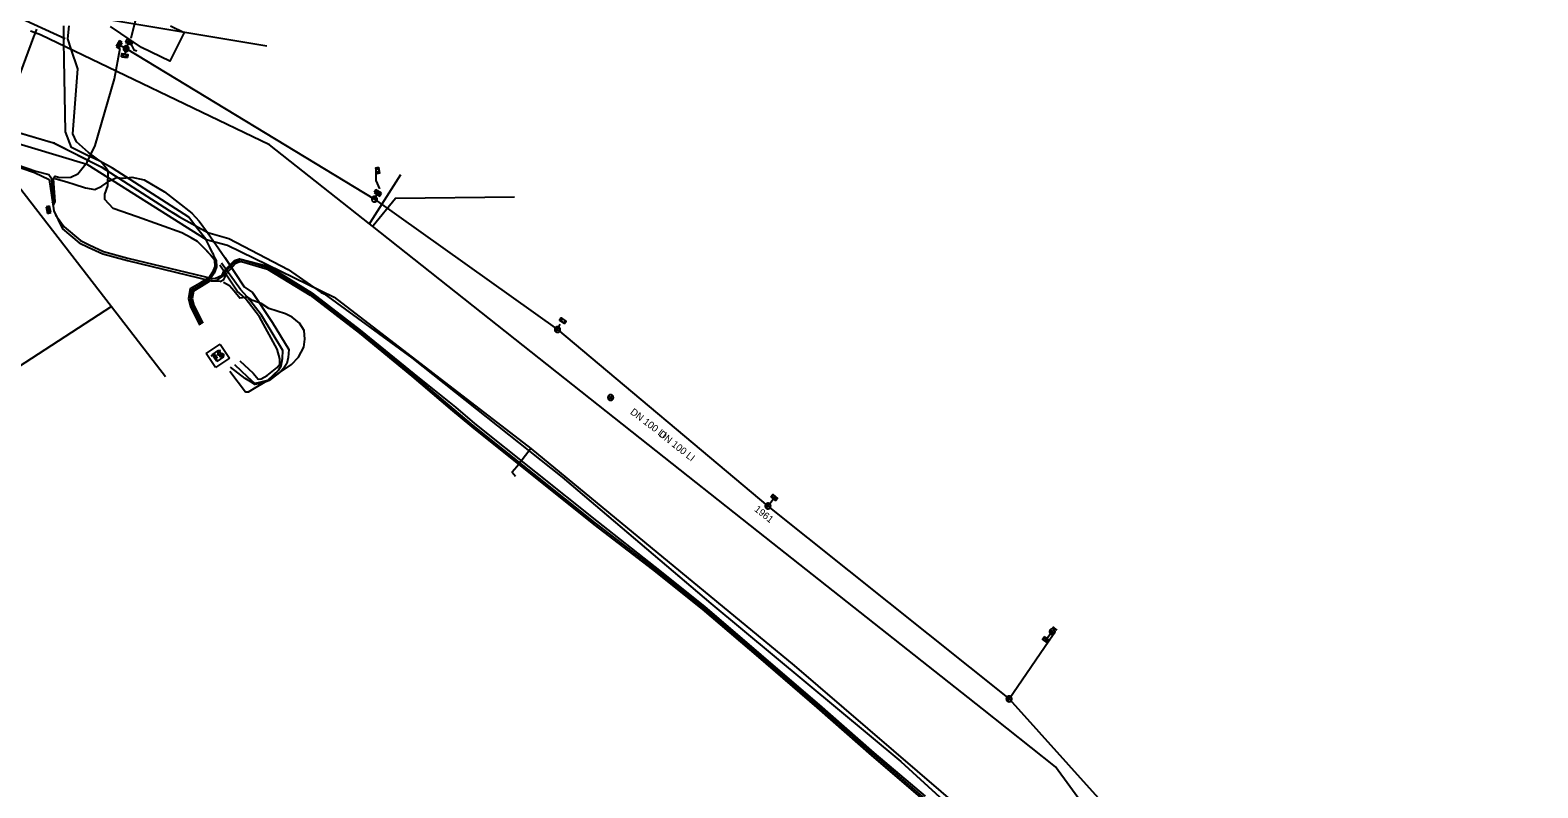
# Model space of a CAD drawing. Extents: x -596024 to -594475, y -1163820 to -1161957.
# Drawn here: x -595938.8 to -595767.7, y -1163354.1 to -1163268.1 of the extents above; entities that cross this region are included whole.
import ezdxf

# ---------------------------------------------------------------- set-up
doc = ezdxf.new("R2010")
doc.units = 0
for name, color, linetype in [('13', 7, 'Continuous'), ('25', 7, 'Continuous'), ('31', 7, 'Continuous'), ('Vrstva 13', 7, 'Continuous'), ('Vrstva 15', 7, 'Continuous'), ('Vrstva 19', 7, 'Continuous'), ('Vrstva 25', 7, 'Continuous'), ('Vrstva 28', 7, 'Continuous'), ('Vrstva 42', 7, 'Continuous'), ('Vrstva 43', 7, 'Continuous'), ('Vrstva 44', 7, 'Continuous'), ('Vrstva 45', 7, 'Continuous'), ('Vrstva 51', 7, 'Continuous'), ('Vrstva 55', 7, 'Continuous')]:
    doc.layers.add(name, color=color, linetype=linetype)

# ---------------------------------------------------------------- blocks, each defined once
blk = doc.blocks.new('NN640')
at = {"layer": '25'}
for points in [[(-1.89, 1.889), (1.889, 1.889)], [(-1.89, -1.89), (-1.89, 1.889)], [(-1.26, 0.787), (-0.221, 0.787)], [(-0.725, 0.787), (-0.725, -0.788)], [(1.197, 0.661), (0.945, 0.787), (0.661, 0.787), (0.409, 0.661), (0.283, 0.472), (0.283, 0.409), (0.409, 0.22), (1.133, -0.158), (1.259, -0.316), (1.259, -0.473), (1.133, -0.662), (0.913, -0.788), (0.629, -0.788), (0.503, -0.725), (0.283, -0.599)], [(1.889, 1.889), (1.889, -1.89)], [(1.889, -1.89), (-1.89, -1.89)]]:
    blk.add_lwpolyline(points, dxfattribs=at)
blk = doc.blocks.new('NN630')
at = {"layer": '31'}
for points in [[(-0.003, -0.7), (-0.703, 0)], [(-0.703, -0.7), (-0.703, 0), (0.697, 0), (0.697, -0.7)], [(-0.003, -0.7), (0.697, 0)], [(-0.703, -0.7), (0.697, -0.7)]]:
    blk.add_lwpolyline(points, dxfattribs=at)
blk = doc.blocks.new('NN400')
at = {"layer": '13'}
for points in [[(-0.63, 0), (0.63, 0)], [(0.632, 0), (0.628, 0.066), (0.618, 0.131), (0.601, 0.195), (0.577, 0.257), (0.547, 0.315), (0.511, 0.37), (0.47, 0.422), (0.423, 0.468), (0.372, 0.51), (0.317, 0.546), (0.258, 0.576), (0.197, 0.599), (0.133, 0.616), (0.068, 0.627), (0.002, 0.63), (-0.064, 0.627), (-0.129, 0.616), (-0.193, 0.599), (-0.255, 0.576), (-0.313, 0.546), (-0.368, 0.51), (-0.42, 0.468), (-0.466, 0.422), (-0.508, 0.37), (-0.544, 0.315), (-0.574, 0.257), (-0.597, 0.195), (-0.614, 0.131), (-0.625, 0.066), (-0.628, 0), (-0.625, -0.066), (-0.614, -0.131), (-0.597, -0.194), (-0.574, -0.256), (-0.544, -0.315), (-0.508, -0.37), (-0.466, -0.421), (-0.42, -0.468), (-0.368, -0.509), (-0.313, -0.545), (-0.255, -0.575), (-0.193, -0.599), (-0.129, -0.616), (-0.064, -0.626), (0.002, -0.63), (0.068, -0.626), (0.133, -0.616), (0.197, -0.599), (0.258, -0.575), (0.317, -0.545), (0.372, -0.509), (0.423, -0.468), (0.47, -0.421), (0.511, -0.37), (0.547, -0.315), (0.577, -0.256), (0.601, -0.194), (0.618, -0.131), (0.628, -0.066), (0.632, 0)], [(0, 0.63), (0, -0.63)]]:
    blk.add_lwpolyline(points, dxfattribs=at)
blk = doc.blocks.new('NN410')
at = {"layer": '13'}
for points in [[(0.005, 0.632), (-0.061, 0.628), (-0.126, 0.618), (-0.19, 0.601), (-0.251, 0.577), (-0.31, 0.547), (-0.365, 0.511), (-0.416, 0.47), (-0.463, 0.423), (-0.505, 0.372), (-0.541, 0.317), (-0.57, 0.258), (-0.594, 0.196), (-0.611, 0.133), (-0.621, 0.068), (-0.625, 0.002), (-0.621, -0.064), (-0.611, -0.129), (-0.594, -0.193), (-0.57, -0.254), (-0.541, -0.313), (-0.505, -0.368), (-0.463, -0.42), (-0.416, -0.466), (-0.365, -0.508), (-0.31, -0.544), (-0.251, -0.574), (-0.19, -0.597), (-0.126, -0.614), (-0.061, -0.625), (0.005, -0.628), (0.071, -0.625), (0.136, -0.614), (0.2, -0.597), (0.261, -0.574), (0.32, -0.544), (0.375, -0.508), (0.427, -0.466), (0.473, -0.42), (0.515, -0.368), (0.55, -0.313), (0.581, -0.254), (0.604, -0.193), (0.621, -0.129), (0.632, -0.064), (0.635, 0.002), (0.632, 0.068), (0.621, 0.133), (0.604, 0.196), (0.58, 0.258), (0.55, 0.317), (0.515, 0.372), (0.473, 0.423), (0.427, 0.47), (0.375, 0.511), (0.32, 0.547), (0.261, 0.577), (0.2, 0.601), (0.136, 0.618), (0.071, 0.628), (0.005, 0.632)], [(0.004, -0.631), (0.004, 0.629)], [(0.958, -0.631), (0.958, 0.629)], [(-0.626, -0.001), (0.633, -0.001)]]:
    blk.add_lwpolyline(points, dxfattribs=at)
blk = doc.blocks.new('NN440')
at = {"layer": '13'}
for points in [[(-0.631, 0), (0.629, 0)], [(0.631, -0.004), (0.627, 0.062), (0.617, 0.127), (0.6, 0.191), (0.577, 0.252), (0.547, 0.311), (0.511, 0.366), (0.469, 0.417), (0.423, 0.464), (0.371, 0.505), (0.316, 0.542), (0.257, 0.571), (0.196, 0.595), (0.132, 0.612), (0.067, 0.622), (0.001, 0.626), (-0.065, 0.622), (-0.13, 0.612), (-0.194, 0.595), (-0.255, 0.571), (-0.314, 0.542), (-0.369, 0.505), (-0.42, 0.464), (-0.467, 0.417), (-0.509, 0.366), (-0.544, 0.311), (-0.574, 0.252), (-0.598, 0.191), (-0.615, 0.127), (-0.626, 0.062), (-0.629, -0.004), (-0.626, -0.07), (-0.615, -0.135), (-0.598, -0.199), (-0.574, -0.26), (-0.544, -0.319), (-0.509, -0.374), (-0.467, -0.426), (-0.42, -0.472), (-0.369, -0.514), (-0.314, -0.55), (-0.255, -0.58), (-0.194, -0.603), (-0.13, -0.62), (-0.065, -0.631), (0.001, -0.634), (0.067, -0.631), (0.132, -0.62), (0.196, -0.603), (0.257, -0.58), (0.316, -0.55), (0.371, -0.514), (0.423, -0.472), (0.469, -0.426), (0.511, -0.374), (0.547, -0.319), (0.577, -0.26), (0.6, -0.199), (0.617, -0.135), (0.627, -0.07), (0.631, -0.004)], [(-0.601, -0.177), (0.57, -0.177)], [(-0.513, -0.325), (0.501, -0.325)], [(-0.375, -0.473), (0.353, -0.473)]]:
    blk.add_lwpolyline(points, dxfattribs=at)
blk = doc.blocks.new('NN620')
at = {"layer": 'Vrstva 28'}
for points in [[(0.752, 0.004), (-0.748, 0.004)], [(-0.748, 0.004), (-0.748, -0.746)], [(0.752, -0.746), (0.752, 0.004)], [(-0.748, -0.746), (0.752, -0.746)], [(0.368, -0.18), (-0.376, -0.18)], [(-0.376, -0.18), (-0.376, -0.558)], [(-0.376, -0.558), (0.368, -0.558)], [(0.321, -0.227), (-0.329, -0.227)], [(-0.329, -0.227), (-0.329, -0.51)], [(-0.329, -0.51), (0.321, -0.51)], [(0.274, -0.274), (-0.281, -0.274)], [(-0.281, -0.274), (-0.281, -0.463)], [(-0.281, -0.463), (0.274, -0.463)], [(0.227, -0.321), (-0.234, -0.321)], [(-0.234, -0.321), (-0.234, -0.416)], [(-0.234, -0.416), (0.227, -0.416)], [(-0.193, -0.369), (0.185, -0.369)], [(0.227, -0.416), (0.227, -0.321)], [(0.274, -0.463), (0.274, -0.274)], [(0.321, -0.51), (0.321, -0.227)], [(0.368, -0.558), (0.368, -0.18)]]:
    blk.add_lwpolyline(points, dxfattribs=at)
blk = doc.blocks.new('VN640')
at = {"layer": '25'}
for points in [[(-1.89, 1.889), (1.889, 1.889)], [(-1.89, -1.89), (-1.89, 1.889)], [(-1.26, 0.787), (-0.221, 0.787)], [(-0.725, 0.787), (-0.725, -0.788)], [(1.197, 0.661), (0.945, 0.787), (0.661, 0.787), (0.409, 0.661), (0.283, 0.472), (0.283, 0.409), (0.409, 0.22), (1.133, -0.158), (1.259, -0.316), (1.259, -0.473), (1.133, -0.662), (0.913, -0.788), (0.629, -0.788), (0.503, -0.725), (0.283, -0.599)], [(1.889, 1.889), (1.889, -1.89)], [(1.889, -1.89), (-1.89, -1.89)]]:
    blk.add_lwpolyline(points, dxfattribs=at)

msp = doc.modelspace()

# ---------------------------------------------------------------- linework, layer by layer
at = {"layer": 'Vrstva 13'}
for p, q in [((-595938.086, -1163267.932), (-595938.244, -1163268.359)), ((-595938.244, -1163268.359), (-595938.75, -1163268.173)), ((-595938.244, -1163268.359), (-595938.408, -1163268.803)), ((-595937.625, -1163268.588), (-595938.244, -1163268.359)), ((-595929.58, -1163299.42), (-595923.438, -1163307.373))]:
    msp.add_line(p, q, dxfattribs=at)
for points in [[(-595937.63, -1163265.552), (-595937.357, -1163265.597), (-595911.942, -1163269.849)], [(-595938.408, -1163268.803), (-595941.679, -1163277.642), (-595941.94, -1163282.32), (-595941.4, -1163284.11), (-595929.58, -1163299.42), (-595968.828, -1163324.958), (-595977.394, -1163331.585)], [(-595728.366, -1163488.51), (-595728.424, -1163488.396), (-595749.643, -1163455.316), (-595750.793, -1163453.647), (-595752.167, -1163451.677), (-595752.658, -1163450.982), (-595763.621, -1163435.372), (-595783.158, -1163406.928), (-595794.584, -1163389.918), (-595822.446, -1163351.687), (-595830.743, -1163345.122), (-595856.129, -1163325.017), (-595868.661, -1163315.115), (-595899.949, -1163290.326), (-595900.29, -1163290.037), (-595911.624, -1163281.082), (-595937.625, -1163268.588)], [(-595900.29, -1163290.037), (-595900.194, -1163289.864), (-595896.741, -1163284.427)], [(-595899.949, -1163290.326), (-595899.858, -1163290.217), (-595897.329, -1163287.132), (-595883.843, -1163286.969)]]:
    msp.add_lwpolyline(points, dxfattribs=at)
at = {"layer": 'Vrstva 19'}
for points in [[(-595976.57, -1163268.8), (-595966.28, -1163270.25), (-595947.71, -1163278.66), (-595932.36, -1163283.27), (-595918.84, -1163291.83), (-595916.4, -1163292.48), (-595904.3, -1163298.37), (-595881.98, -1163315.56), (-595852.11, -1163340.18), (-595824.19, -1163364.19), (-595799.09, -1163400.08), (-595772.06, -1163439.83), (-595755.81, -1163463.13), (-595753.4, -1163467.1), (-595747.38, -1163476.34), (-595734.81, -1163496.09), (-595731.58, -1163501.08), (-595721.32, -1163517.68), (-595699.46, -1163552.28), (-595691.87, -1163560.24), (-595680.77, -1163572.32), (-595671.06, -1163594.27)], [(-595881.98, -1163315.56), (-595882.59, -1163316.35)], [(-595882.59, -1163316.35), (-595883.56, -1163317.63), (-595884.1, -1163318.25), (-595883.72, -1163318.71)]]:
    msp.add_lwpolyline(points, dxfattribs=at)
at = {"layer": 'Vrstva 25'}
for p, q in [((-595945.683, -1163278.041), (-595936.152, -1163280.837)), ((-595936.047, -1163280.889), (-595936.152, -1163280.837)), ((-595936.047, -1163280.889), (-595930.74, -1163283.586)), ((-595930.74, -1163283.586), (-595923.022, -1163288.534)), ((-595923.022, -1163288.534), (-595922.203, -1163289.006)), ((-595922.203, -1163289.006), (-595921.838, -1163289.265)), ((-595921.838, -1163289.265), (-595918.641, -1163291.017)), ((-595918.641, -1163291.017), (-595916.242, -1163291.728)), ((-595916.242, -1163291.728), (-595909.505, -1163295.218)), ((-595909.505, -1163295.218), (-595905.784, -1163297.857)), ((-595905.784, -1163297.857), (-595905.436, -1163298.008)), ((-595905.436, -1163298.008), (-595895.478, -1163305.265)), ((-595895.478, -1163305.265), (-595878.421, -1163318.816)), ((-595878.421, -1163318.816), (-595877.408, -1163319.663)), ((-595877.408, -1163319.663), (-595861.56, -1163333.174)), ((-595861.56, -1163333.174), (-595839.991, -1163351.11)), ((-595839.991, -1163351.11), (-595829.484, -1163360.692))]:
    msp.add_line(p, q, dxfattribs=at)
msp.add_lwpolyline([(-595945.683, -1163278.041), (-595936.152, -1163280.837), (-595930.74, -1163283.586), (-595923.022, -1163288.534), (-595921.838, -1163289.265), (-595918.641, -1163291.017), (-595916.242, -1163291.728), (-595909.505, -1163295.218), (-595905.784, -1163297.857), (-595905.436, -1163298.008), (-595895.478, -1163305.265), (-595878.421, -1163318.816), (-595861.56, -1163333.174), (-595839.991, -1163351.11), (-595829.484, -1163360.692), (-595819.586, -1163370.216), (-595815.383, -1163374.422), (-595810.88, -1163380.577), (-595801.657, -1163394.554), (-595794.722, -1163403.944), (-595786.54, -1163415.206), (-595778.839, -1163426.631), (-595768.97, -1163441.158)], dxfattribs=at)
at = {"layer": 'Vrstva 42'}
for points in [[(-595927.363, -1163269.625), (-595927.037, -1163270.279), (-595926.691, -1163270.389)], [(-595936.14, -1163284.924), (-595935.958, -1163284.63), (-595935.42, -1163284.77), (-595934.19, -1163284.73), (-595933.4, -1163284.38), (-595932.32, -1163283.04), (-595931.44, -1163281.14), (-595929.24, -1163273.57), (-595928.599, -1163270.115)], [(-595945.4, -1163281.57), (-595938.14, -1163284.06), (-595936.674, -1163284.443), (-595936.34, -1163284.936)], [(-595936.252, -1163287.653), (-595936.181, -1163287.474), (-595936.34, -1163284.936)], [(-595936.153, -1163287.945), (-595935.979, -1163287.506), (-595936.14, -1163284.924)], [(-595899.12, -1163286.062), (-595899.529, -1163285.143), (-595899.517, -1163284.017)], [(-595935.929, -1163289.04), (-595934.94, -1163290.38), (-595933.1, -1163291.94), (-595932.11, -1163292.44), (-595930.49, -1163293.18), (-595927.7, -1163293.93), (-595918.25, -1163296.2), (-595917.85, -1163296.26), (-595917, -1163295.86), (-595916.82, -1163295.43), (-595915.61, -1163294.2), (-595915.04, -1163294.02), (-595911.67, -1163294.9), (-595906.78, -1163297.93), (-595901.36, -1163302.12), (-595895.26, -1163307.07), (-595890.53, -1163310.88), (-595888.38, -1163312.7), (-595874.53, -1163323.77), (-595867.91, -1163329), (-595862.29, -1163333.51), (-595855.89, -1163338.97), (-595849.28, -1163344.67), (-595843.06, -1163350.12), (-595837.22, -1163355.05)], [(-595878.954, -1163302.049), (-595878.663, -1163301.454)], [(-595855.075, -1163322.09), (-595854.256, -1163321.016)]]:
    msp.add_lwpolyline(points, dxfattribs=at)
at = {"layer": 'Vrstva 44'}
for p, q in [((-595918.95, -1163292.93), (-595919.82, -1163292.06)), ((-595917.78, -1163294.22), (-595918.95, -1163292.93)), ((-595918.01, -1163295.59), (-595917.74, -1163294.91)), ((-595917.78, -1163294.22), (-595917.916, -1163293.834)), ((-595917.74, -1163294.91), (-595917.78, -1163294.22)), ((-595918.58, -1163296.41), (-595918.01, -1163295.59)), ((-595918.58, -1163296.41), (-595918.227, -1163296.476))]:
    msp.add_line(p, q, dxfattribs=at)
for points in [[(-595918.09, -1163293.34), (-595918.41, -1163292.7), (-595918.85, -1163291.8), (-595919.91, -1163290.47), (-595920.79, -1163289.3), (-595929.46, -1163283.71), (-595930.878, -1163282.937), (-595932.38, -1163282.24), (-595934.09, -1163281.37), (-595934.8, -1163279.6), (-595934.93, -1163271.4), (-595934.98, -1163269.43), (-595934.97, -1163267.56)], [(-595919.82, -1163292.06), (-595920.52, -1163291.62), (-595921.59, -1163291.07), (-595926.66, -1163289.27), (-595929.37, -1163288.29), (-595930.32, -1163287.27), (-595930.31, -1163286.66), (-595929.98, -1163285.74), (-595929.95, -1163284.07), (-595930.17, -1163283.74), (-595930.73, -1163283.01), (-595932.17, -1163281.96), (-595933.53, -1163280.72), (-595933.94, -1163279.82), (-595933.4, -1163272.43), (-595934.16, -1163270.21), (-595934.54, -1163269.03), (-595934.37, -1163267.58)], [(-595945.98, -1163281.59), (-595938.32, -1163284.21), (-595936.66, -1163285.01)], [(-595936.66, -1163285.01), (-595936.12, -1163288.56), (-595935.13, -1163290.6), (-595933.23, -1163292.2), (-595932.23, -1163292.7), (-595930.56, -1163293.46), (-595927.77, -1163294.21), (-595918.26, -1163296.51), (-595917.69, -1163296.53), (-595916.824, -1163295.926), (-595916.697, -1163295.577), (-595915.569, -1163294.346), (-595915.127, -1163294.163), (-595914.783, -1163294.108), (-595911.769, -1163295.008), (-595906.893, -1163297.998), (-595901.298, -1163302.322), (-595895.376, -1163307.203), (-595890.726, -1163311.113), (-595888.567, -1163312.933), (-595874.708, -1163324.011), (-595868.038, -1163329.151), (-595862.416, -1163333.663), (-595856.005, -1163339.104), (-595849.394, -1163344.805), (-595843.174, -1163350.254), (-595837.364, -1163355.245)], [(-595935.95, -1163284.906), (-595934.54, -1163285.32), (-595933.809, -1163285.551), (-595932.51, -1163285.94), (-595931.46, -1163286.16), (-595930.67, -1163285.78), (-595929.78, -1163285.18), (-595928.99, -1163284.78), (-595928.22, -1163284.86), (-595927.25, -1163284.74), (-595925.86, -1163285.04), (-595923.56, -1163286.41), (-595920.45, -1163288.84), (-595919.63, -1163289.75), (-595918.66, -1163291.03), (-595916.7, -1163293.87), (-595914.5, -1163297.21), (-595913.56, -1163297.85), (-595911.33, -1163301.23), (-595909.45, -1163304.3), (-595909.52, -1163305.21), (-595909.66, -1163305.89), (-595909.96, -1163306.37), (-595910.49, -1163306.92), (-595911.677, -1163307.841), (-595912.324, -1163308.094), (-595913.314, -1163308.296), (-595913.76, -1163307.98), (-595914.383, -1163307.592), (-595916.074, -1163306.339)], [(-595919.82, -1163292.06), (-595919.24, -1163292.63), (-595918.95, -1163292.93), (-595918.35, -1163293.58), (-595917.949, -1163294.03), (-595917.88, -1163294.226), (-595917.841, -1163294.894), (-595918.099, -1163295.542), (-595918.454, -1163296.053), (-595918.69, -1163296.243), (-595919.585, -1163296.83), (-595920.63, -1163297.433), (-595920.835, -1163298.527), (-595920.588, -1163299.461), (-595919.537, -1163301.542)], [(-595918.09, -1163293.34), (-595917.916, -1163293.834), (-595917.68, -1163294.214), (-595917.639, -1163294.926), (-595917.921, -1163295.638), (-595918.35, -1163296.254), (-595918.58, -1163296.41), (-595919.48, -1163297), (-595920.45, -1163297.56), (-595920.63, -1163298.52), (-595920.4, -1163299.39), (-595919.37, -1163301.43)], [(-595914.989, -1163305.612), (-595913.494, -1163306.996), (-595912.93, -1163307.67), (-595912.59, -1163307.63), (-595911.89, -1163307.27), (-595910.75, -1163306.37), (-595910.45, -1163305.99), (-595910.46, -1163305.39), (-595910.75, -1163304.27), (-595912.79, -1163300.59), (-595914.41, -1163298.5), (-595915.29, -1163297.71), (-595917.28, -1163294.74)], [(-595917.25, -1163296.58), (-595916.803, -1163296.372), (-595916.636, -1163295.994), (-595916.523, -1163295.683), (-595915.451, -1163294.514), (-595915.073, -1163294.357), (-595914.797, -1163294.312), (-595911.851, -1163295.192), (-595907.007, -1163298.162), (-595901.422, -1163302.478), (-595895.504, -1163307.357), (-595890.854, -1163311.267), (-595888.693, -1163313.087), (-595874.832, -1163324.169), (-595868.162, -1163329.309), (-595862.544, -1163333.817), (-595856.135, -1163339.256), (-595849.526, -1163344.955), (-595843.306, -1163350.406), (-595837.496, -1163355.395)], [(-595915.617, -1163306.033), (-595914.145, -1163307.432), (-595913.33, -1163308.15), (-595912.88, -1163308.08), (-595911.84, -1163307.79), (-595910.59, -1163306.64), (-595910.3, -1163306.17), (-595910.15, -1163305.34), (-595910.12, -1163304.44), (-595912.53, -1163300.41), (-595914.19, -1163298.35), (-595914.93, -1163297.51), (-595917.09, -1163294.5)], [(-595917.25, -1163296.58), (-595917.83, -1163296.55), (-595918.227, -1163296.476), (-595918.47, -1163296.577), (-595919.375, -1163297.17), (-595920.27, -1163297.687), (-595920.425, -1163298.513), (-595920.212, -1163299.319), (-595919.203, -1163301.316)], [(-595916.146, -1163306.782), (-595914.35, -1163309.12), (-595914.02, -1163309.12), (-595913.16, -1163308.58), (-595911.66, -1163307.73), (-595909.15, -1163306), (-595908.34, -1163305.2), (-595907.74, -1163304.06), (-595907.61, -1163303.13), (-595907.71, -1163302.15), (-595908.23, -1163301.31), (-595909.06, -1163300.66), (-595909.81, -1163300.27), (-595911.72, -1163299.65), (-595912.59, -1163299.11), (-595913.53, -1163298.75), (-595914.08, -1163298.36), (-595915.02, -1163298.49), (-595915.63, -1163297.68), (-595916.19, -1163297.08), (-595916.85, -1163296.71)]]:
    msp.add_lwpolyline(points, dxfattribs=at)
at = {"layer": 'Vrstva 51'}
for points in [[(-595927.344, -1163268.949), (-595927.328, -1163268.914), (-595918.844, -1163234.972), (-595918.386, -1163234.417)], [(-595927.9, -1163270.155), (-595927.634, -1163269.579)], [(-595928.457, -1163269.843), (-595928.327, -1163269.91), (-595927.9, -1163270.155)], [(-595927.9, -1163270.155), (-595928.048, -1163270.776)], [(-595927.9, -1163270.155), (-595899.726, -1163287.251)], [(-595899.726, -1163287.251), (-595899.427, -1163286.695)], [(-595899.726, -1163287.251), (-595878.955, -1163302.05), (-595855.075, -1163322.09), (-595827.71, -1163343.993), (-595804.488, -1163369.849), (-595784.23, -1163399.906), (-595766.002, -1163426.619), (-595746.884, -1163455.615), (-595730.422, -1163479.578), (-595729.966, -1163480.243)], [(-595827.71, -1163343.993), (-595822.691, -1163336.675), (-595822.804, -1163336.358), (-595823.632, -1163337.409)]]:
    msp.add_lwpolyline(points, dxfattribs=at)
at = {"layer": 'Vrstva 55'}
for points in [[(-595978.69, -1163202.35), (-595978.39, -1163216.95), (-595976.43, -1163235.13), (-595973, -1163244.06), (-595970.38, -1163247.24), (-595967.93, -1163249.42), (-595957.31, -1163254.13), (-595950.76, -1163257.2), (-595946.29, -1163262.21), (-595940.63, -1163266.37), (-595934.83, -1163268.99)], [(-595922.878, -1163267.57), (-595921.327, -1163268.328), (-595922.947, -1163271.564), (-595926.164, -1163270.017), (-595929.7, -1163267.629)]]:
    msp.add_lwpolyline(points, dxfattribs=at)

# ---------------------------------------------------------------- block references
at = {"layer": 'Vrstva 43'}
for name, p, xscale, yscale, rotation in [('NN620', (-595928.541, -1163269.766), 0.49999999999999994, 0.5000000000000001, -121.00000000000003), ('NN620', (-595927.634, -1163269.579), 0.49999999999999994, 0.5000000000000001, 156), ('NN630', (-595928.048, -1163270.776), 0.5000000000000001, 0.5000000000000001, -9.000000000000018), ('NN440', (-595927.9, -1163270.154), 0.49999999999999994, 0.5000000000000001, -121.00000000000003), ('NN630', (-595899.517, -1163284.017), 0.5000000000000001, 0.5, 102), ('NN620', (-595899.427, -1163286.695), 0.49999999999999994, 0.5000000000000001, 149), ('NN620', (-595936.901, -1163288.49), 0.5, 0.5, 103), ('NN440', (-595899.726, -1163287.25), 0.5, 0.5, 147), ('NN440', (-595878.954, -1163302.049), 0.49999999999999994, 0.5000000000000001, -125.00000000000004), ('NN630', (-595878.24, -1163300.929), 0.5, 0.5, -35.00000000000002), ('NN640', (-595917.503, -1163305.039), 0.5, 0.5, 34), ('NN400', (-595872.923, -1163309.77), 0.49999999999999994, 0.49999999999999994, 143), ('NN630', (-595854.256, -1163321.016), 0.5, 0.5, -40.00000000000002), ('NN440', (-595855.075, -1163322.089), 0.5, 0.5, -130), ('NN410', (-595822.805, -1163336.359), 0.49999999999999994, 0.5000000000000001, 51), ('NN630', (-595823.632, -1163337.409), 0.49999999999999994, 0.5000000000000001, 141), ('NN440', (-595827.709, -1163343.992), 0.5, 0.5, -127.99999999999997)]:
    msp.add_blockref(name, p, dxfattribs=dict(at, xscale=xscale, yscale=yscale, rotation=rotation))
at = {"layer": 'Vrstva 45', "xscale": 0.25, "yscale": 0.25, "rotation": 34}
msp.add_blockref('VN640', (-595917.503, -1163305.039), dxfattribs=at)

# ---------------------------------------------------------------- texts
at = {"layer": 'Vrstva 15'}
for s, rotation, p in [('DN 100 LI', 322.80442, (-595870.774, -1163311.552)), ('DN 100 LI', 321.68671, (-595867.53, -1163314.078)), ('1961', 321.60121, (-595856.697, -1163322.587))]:
    msp.add_text(s, height=0.8, rotation=rotation, dxfattribs=at).set_placement(p)

doc.saveas('drawing.dxf')
